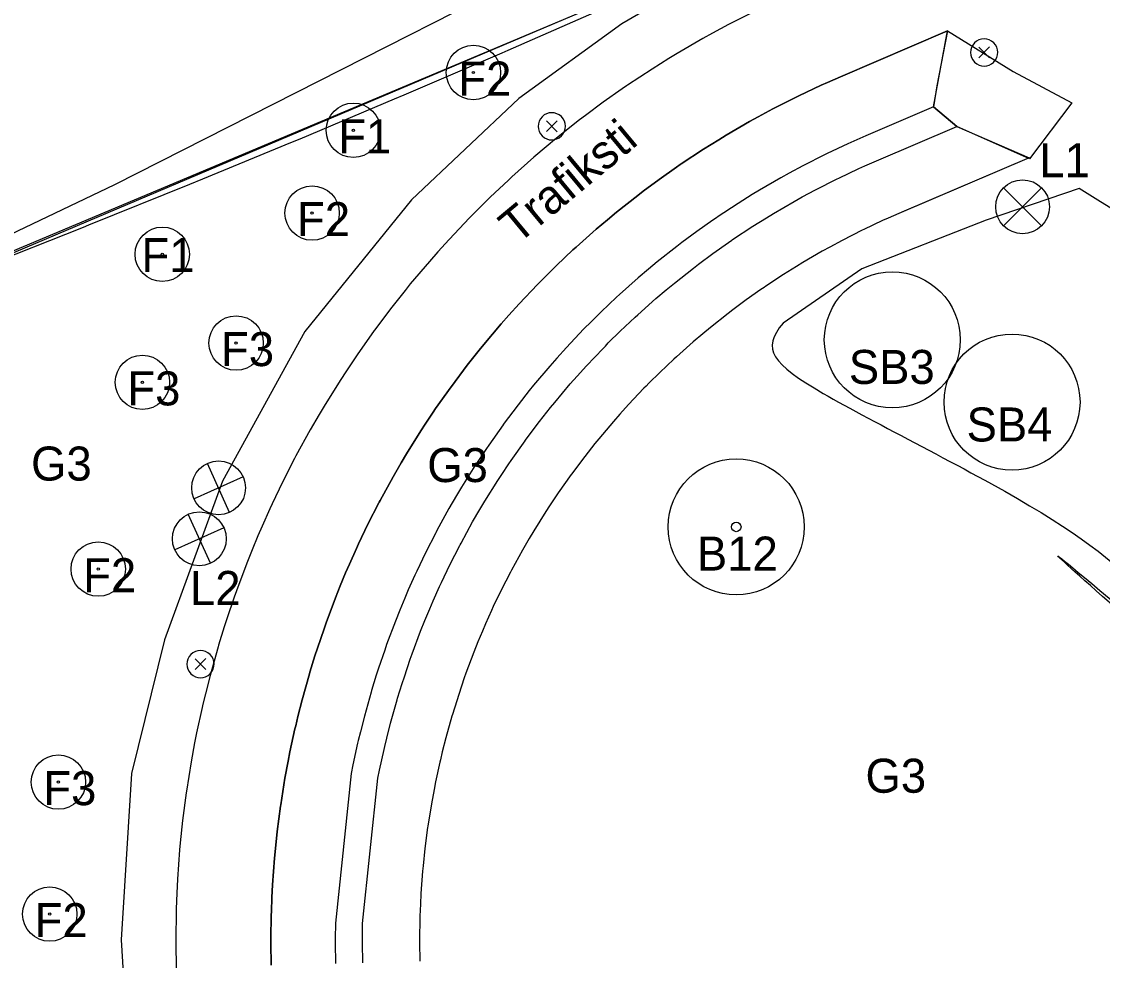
# Model space of a CAD drawing. Extents: x 0 to 512122, y 0 to 6212554.
# Drawn here: x 511727.9 to 511767.64, y 6211766.14 to 6211800.64 of the extents above; entities that cross this region are included whole.
import ezdxf

# ---------------------------------------------------------------- set-up
doc = ezdxf.new("R2010")
doc.units = 0
for name, color, linetype in [('_lights', 7, 'Continuous'), ('_Låge L1', 7, 'Continuous'), ('_Låge L2', 7, 'Continuous'), ('_ny fruit trees', 7, 'Continuous'), ('L40 jord udlagt muld og grøft', 7, 'Continuous'), ('MatrikelnummerMaster', 7, 'Continuous'), ('Skel', 7, 'Continuous'), ('TV_U_AFM_Symbl_Gul', 7, 'Continuous'), ('TV_U_LYS_Mastenummer', 7, 'Continuous')]:
    doc.layers.add(name, color=color, linetype=linetype)

# ---------------------------------------------------------------- blocks, each defined once
blk = doc.blocks.new('SOLITAIRE TREES')
at = {"layer": 'Skel'}
for radius in [2, 0.141]:
    blk.add_circle((0, 0), radius, dxfattribs=at)

msp = doc.modelspace()

# ---------------------------------------------------------------- linework, layer by layer
at = {"layer": '_lights'}
for p, q in [((511763.098, 6211799.706), (511763.492, 6211799.311)), ((511763.496, 6211799.71), (511763.102, 6211799.315)), ((511747.198, 6211796.991), (511747.592, 6211796.597)), ((511747.596, 6211796.995), (511747.202, 6211796.6)), ((511734.281, 6211777.225), (511734.675, 6211776.831)), ((511734.679, 6211777.229), (511734.285, 6211776.835))]:
    msp.add_line(p, q, dxfattribs=at)
for centre, start, end in [((511763.295, 6211799.509), 315.5636, 315), ((511763.295, 6211799.509), 315, 315.5636), ((511747.395, 6211796.794), 315.5636, 315), ((511747.395, 6211796.794), 315, 315.5636), ((511734.478, 6211777.028), 315.5636, 315), ((511734.478, 6211777.028), 315, 315.5636)]:
    msp.add_arc(centre, 0.5, start, end, dxfattribs=at)
at = {"layer": '_Låge L1'}
for p, q in [((511765.406, 6211794.536), (511764.008, 6211793.138)), ((511764.008, 6211794.536), (511765.406, 6211793.138))]:
    msp.add_line(p, q, dxfattribs=at)
msp.add_circle((511764.707, 6211793.837), 0.989, dxfattribs=at)
at = {"layer": '_Låge L2'}
for p, q in [((511735.549, 6211782.603), (511734.735, 6211784.406)), ((511736.043, 6211783.911), (511734.241, 6211783.098)), ((511734.841, 6211780.733), (511734.027, 6211782.535)), ((511735.335, 6211782.041), (511733.533, 6211781.227))]:
    msp.add_line(p, q, dxfattribs=at)
for centre in [(511735.142, 6211783.505), (511734.434, 6211781.634)]:
    msp.add_circle(centre, 0.989, dxfattribs=at)
at = {"layer": '_ny fruit trees'}
for centre, radius in [((511744.513, 6211798.772), 1), ((511744.513, 6211798.772), 0.0426), ((511740.097, 6211796.648), 1), ((511740.097, 6211796.648), 0.0426), ((511738.582, 6211793.605), 1), ((511738.582, 6211793.605), 0.0426), ((511733.071, 6211792.09), 1), ((511733.071, 6211792.09), 0.0426), ((511735.787, 6211788.829), 1), ((511735.787, 6211788.829), 0.0426), ((511732.34, 6211787.384), 1), ((511732.34, 6211787.384), 0.0426), ((511730.715, 6211780.52), 1), ((511730.715, 6211780.52), 0.0426), ((511729.251, 6211772.691), 1), ((511729.251, 6211772.691), 0.0426), ((511728.933, 6211767.84), 1), ((511728.933, 6211767.84), 0.0426)]:
    msp.add_circle(centre, radius, dxfattribs=at)
at = {"layer": 'L40 jord udlagt muld og grøft'}
for points in [[(511716.684, 6211807.008), (511745.321, 6211818.788), (511750.168, 6211811.842), (511756.678, 6211804.446), (511723.011, 6211790.293), (511716.684, 6211807.008)], [(511726.45, 6211791.621), (511730.172, 6211793.09), (511730.368, 6211793.168), (511734.084, 6211794.667), (511734.557, 6211794.861), (511737.801, 6211796.198), (511738.137, 6211796.337), (511741.615, 6211797.801), (511741.965, 6211797.948), (511745.576, 6211799.5), (511745.795, 6211799.594), (511749.456, 6211801.199), (511757.004, 6211804.634), (511758.258, 6211803.606), (511758.576, 6211803.35), (511758.674, 6211803.272), (511759.018, 6211803.002), (511759.055, 6211802.974), (511759.094, 6211802.943), (511759.162, 6211802.894)], [(511754.868, 6211801.026), (511753.899, 6211800.535), (511753.304, 6211800.216), (511752.945, 6211800.017), (511752.007, 6211799.471), (511751.701, 6211799.286), (511751.084, 6211798.899), (511750.178, 6211798.301), (511750.145, 6211798.279), (511749.987, 6211798.17), (511749.289, 6211797.677), (511748.64, 6211797.197), (511748.419, 6211797.028), (511747.567, 6211796.355), (511747.19, 6211796.043), (511746.736, 6211795.657), (511745.924, 6211794.936), (511745.798, 6211794.82), (511745.133, 6211794.192), (511744.601, 6211793.666), (511744.467, 6211793.531), (511744.364, 6211793.426), (511743.617, 6211792.638), (511743.2, 6211792.178), (511742.893, 6211791.829), (511742.192, 6211791), (511742.001, 6211790.765), (511741.516, 6211790.151), (511740.872, 6211789.296), (511740.863, 6211789.283), (511740.236, 6211788.397), (511740.135, 6211788.248), (511739.817, 6211787.773), (511739.635, 6211787.493), (511739.059, 6211786.573), (511738.836, 6211786.2), (511738.51, 6211785.636), (511737.988, 6211784.684), (511737.95, 6211784.613), (511737.934, 6211784.581), (511737.493, 6211783.718), (511737.111, 6211782.921), (511737.027, 6211782.737), (511736.742, 6211782.101), (511736.588, 6211781.744), (511736.371, 6211781.222), (511736.178, 6211780.739), (511735.797, 6211779.722), (511735.714, 6211779.489), (511735.445, 6211778.695), (511735.348, 6211778.394), (511735.142, 6211777.726), (511735.122, 6211777.659), (511734.83, 6211776.613), (511734.658, 6211775.938), (511734.567, 6211775.56), (511734.538, 6211775.435), (511734.334, 6211774.499), (511734.26, 6211774.128), (511734.132, 6211773.433), (511733.961, 6211772.361), (511733.952, 6211772.3), (511733.82, 6211771.284), (511733.733, 6211770.46), (511733.71, 6211770.204), (511733.63, 6211769.121), (511733.604, 6211768.612), (511733.582, 6211768.037), (511733.578, 6211767.89), (511733.565, 6211766.951), (511733.565, 6211766.759), (511733.579, 6211765.865)], [(511761.949, 6211800.299), (511758.014, 6211798.618), (511757.536, 6211798.41), (511757.3, 6211798.303), (511756.483, 6211797.92), (511756.408, 6211797.883), (511755.529, 6211797.437), (511754.988, 6211797.147), (511754.663, 6211796.967), (511753.811, 6211796.472), (511753.533, 6211796.303), (511752.973, 6211795.952), (511752.15, 6211795.409), (511752.121, 6211795.389), (511751.977, 6211795.29), (511751.344, 6211794.843), (511750.754, 6211794.407), (511750.554, 6211794.254), (511749.78, 6211793.642), (511749.438, 6211793.359), (511749.025, 6211793.009), (511748.288, 6211792.354), (511748.174, 6211792.249), (511747.57, 6211791.679), (511747.087, 6211791.201), (511746.965, 6211791.078), (511746.872, 6211790.983), (511746.194, 6211790.268), (511745.815, 6211789.85), (511745.536, 6211789.533), (511744.9, 6211788.78), (511744.727, 6211788.567), (511744.286, 6211788.01), (511743.702, 6211787.233), (511743.694, 6211787.222), (511743.124, 6211786.417), (511743.032, 6211786.282), (511742.743, 6211785.85), (511742.578, 6211785.597), (511742.056, 6211784.761), (511741.853, 6211784.423), (511741.557, 6211783.91), (511741.083, 6211783.046), (511741.049, 6211782.982), (511741.034, 6211782.953), (511740.634, 6211782.169), (511740.287, 6211781.445), (511740.21, 6211781.279), (511739.952, 6211780.701), (511739.812, 6211780.377), (511739.615, 6211779.903), (511739.44, 6211779.464), (511739.094, 6211778.542), (511739.019, 6211778.33), (511738.774, 6211777.609), (511738.686, 6211777.335), (511738.5, 6211776.729), (511738.482, 6211776.668), (511738.216, 6211775.719), (511738.06, 6211775.106), (511737.977, 6211774.762), (511737.951, 6211774.649), (511737.766, 6211773.8), (511737.699, 6211773.462), (511737.583, 6211772.831), (511737.427, 6211771.858), (511737.419, 6211771.803), (511737.299, 6211770.88), (511737.22, 6211770.132), (511737.199, 6211769.9), (511737.127, 6211768.917), (511737.103, 6211768.454), (511737.083, 6211767.932), (511737.08, 6211767.799), (511737.068, 6211766.947), (511737.068, 6211766.772), (511737.08, 6211765.961)], [(511737.08, 6211765.961), (511737.068, 6211766.772), (511737.068, 6211766.947), (511737.08, 6211767.799), (511737.083, 6211767.932), (511737.103, 6211768.454), (511737.127, 6211768.917), (511737.199, 6211769.9), (511737.22, 6211770.132), (511737.299, 6211770.88), (511737.419, 6211771.803), (511737.427, 6211771.858), (511737.583, 6211772.831), (511737.699, 6211773.462), (511737.766, 6211773.8), (511737.951, 6211774.649), (511737.977, 6211774.762), (511738.06, 6211775.106), (511738.216, 6211775.719), (511738.482, 6211776.668), (511738.5, 6211776.729), (511738.686, 6211777.335), (511738.774, 6211777.609), (511739.019, 6211778.33), (511739.094, 6211778.542), (511739.44, 6211779.464), (511739.615, 6211779.903), (511739.812, 6211780.377), (511739.952, 6211780.701), (511740.21, 6211781.279), (511740.287, 6211781.445), (511740.634, 6211782.169), (511741.034, 6211782.953), (511741.049, 6211782.982), (511741.083, 6211783.046), (511741.557, 6211783.91), (511741.853, 6211784.423), (511742.056, 6211784.761), (511742.578, 6211785.597), (511742.743, 6211785.85), (511743.032, 6211786.282), (511743.124, 6211786.417), (511743.694, 6211787.222), (511743.702, 6211787.233), (511744.286, 6211788.01), (511744.727, 6211788.567), (511744.9, 6211788.78), (511745.536, 6211789.533), (511745.815, 6211789.85), (511746.194, 6211790.268), (511746.872, 6211790.983), (511746.965, 6211791.078), (511747.087, 6211791.201), (511747.57, 6211791.679), (511748.174, 6211792.249), (511748.288, 6211792.354), (511749.025, 6211793.009), (511749.438, 6211793.359), (511749.78, 6211793.642), (511750.554, 6211794.254), (511750.754, 6211794.407), (511751.344, 6211794.843), (511751.977, 6211795.29), (511752.121, 6211795.389), (511752.15, 6211795.409), (511752.973, 6211795.952), (511753.533, 6211796.303), (511753.811, 6211796.472), (511754.663, 6211796.967), (511754.988, 6211797.147), (511755.529, 6211797.437), (511756.408, 6211797.883), (511756.483, 6211797.92), (511757.3, 6211798.303), (511757.536, 6211798.41), (511758.014, 6211798.618), (511761.949, 6211800.299), (511761.553, 6211798.279), (511761.434, 6211797.507), (511758.943, 6211796.443), (511758.498, 6211796.249), (511758.278, 6211796.15), (511757.517, 6211795.793), (511757.447, 6211795.759), (511756.629, 6211795.344), (511756.125, 6211795.073), (511755.822, 6211794.905), (511755.028, 6211794.444), (511754.769, 6211794.287), (511754.248, 6211793.96), (511753.481, 6211793.454), (511753.454, 6211793.435), (511753.32, 6211793.344), (511752.73, 6211792.927), (511752.181, 6211792.521), (511751.994, 6211792.378), (511751.274, 6211791.808), (511750.955, 6211791.545), (511750.57, 6211791.219), (511749.884, 6211790.609), (511749.777, 6211790.511), (511749.215, 6211789.98), (511748.765, 6211789.535), (511748.652, 6211789.42), (511748.565, 6211789.332), (511747.933, 6211788.665), (511747.581, 6211788.276), (511747.321, 6211787.981), (511746.728, 6211787.28), (511746.567, 6211787.082), (511746.156, 6211786.562), (511745.612, 6211785.839), (511745.604, 6211785.828), (511745.074, 6211785.079), (511744.988, 6211784.953), (511744.719, 6211784.551), (511744.565, 6211784.314), (511744.079, 6211783.536), (511743.89, 6211783.221), (511743.614, 6211782.744), (511743.173, 6211781.939), (511743.141, 6211781.879), (511743.127, 6211781.852), (511742.755, 6211781.122), (511742.432, 6211780.448), (511742.36, 6211780.293), (511742.119, 6211779.755), (511741.989, 6211779.453), (511741.805, 6211779.011), (511741.642, 6211778.603), (511741.32, 6211777.743), (511741.25, 6211777.546), (511741.022, 6211776.874), (511740.94, 6211776.62), (511740.767, 6211776.055), (511740.75, 6211775.998), (511740.502, 6211775.114), (511740.356, 6211774.543), (511740.28, 6211774.223), (511740.255, 6211774.117), (511740.083, 6211773.326), (511740.021, 6211773.012), (511739.44, 6211767.503), (511739.433, 6211766.943), (511739.433, 6211766.78), (511739.444, 6211766.025)], [(511761.949, 6211800.299), (511761.553, 6211798.279), (511761.434, 6211797.507), (511762.286, 6211796.784), (511764.951, 6211795.637)], [(511740.444, 6211766.052), (511740.433, 6211766.784), (511740.433, 6211766.941), (511740.44, 6211767.49), (511741.004, 6211772.83), (511741.063, 6211773.126), (511741.23, 6211773.892), (511741.253, 6211773.995), (511741.328, 6211774.304), (511741.469, 6211774.858), (511741.709, 6211775.714), (511741.725, 6211775.77), (511741.893, 6211776.317), (511741.973, 6211776.564), (511742.193, 6211777.214), (511742.261, 6211777.405), (511742.573, 6211778.238), (511742.732, 6211778.634), (511742.909, 6211779.062), (511743.035, 6211779.354), (511743.269, 6211779.876), (511743.338, 6211780.026), (511743.651, 6211780.679), (511744.012, 6211781.387), (511744.026, 6211781.412), (511744.057, 6211781.471), (511744.484, 6211782.251), (511744.752, 6211782.713), (511744.934, 6211783.018), (511745.406, 6211783.772), (511745.555, 6211784.001), (511745.815, 6211784.391), (511745.898, 6211784.513), (511746.412, 6211785.239), (511746.42, 6211785.249), (511746.947, 6211785.95), (511747.345, 6211786.453), (511747.501, 6211786.646), (511748.075, 6211787.325), (511748.327, 6211787.611), (511748.669, 6211787.988), (511749.281, 6211788.633), (511749.365, 6211788.719), (511749.474, 6211788.83), (511749.911, 6211789.261), (511750.455, 6211789.776), (511750.559, 6211789.871), (511751.224, 6211790.462), (511751.596, 6211790.778), (511751.905, 6211791.033), (511752.603, 6211791.585), (511752.784, 6211791.723), (511753.316, 6211792.117), (511753.888, 6211792.521), (511754.017, 6211792.609), (511754.044, 6211792.628), (511754.787, 6211793.118), (511755.292, 6211793.434), (511755.543, 6211793.587), (511756.312, 6211794.033), (511756.605, 6211794.196), (511757.093, 6211794.458), (511757.887, 6211794.86), (511757.954, 6211794.893), (511758.691, 6211795.24), (511758.905, 6211795.336), (511759.336, 6211795.524), (511762.286, 6211796.784), (511761.434, 6211797.507), (511758.943, 6211796.443), (511758.498, 6211796.249), (511758.278, 6211796.15), (511757.517, 6211795.793), (511757.447, 6211795.759), (511756.629, 6211795.344), (511756.125, 6211795.073), (511755.822, 6211794.905), (511755.028, 6211794.444), (511754.769, 6211794.287), (511754.248, 6211793.96), (511753.481, 6211793.454), (511753.454, 6211793.435), (511753.32, 6211793.344), (511752.73, 6211792.927), (511752.181, 6211792.521), (511751.994, 6211792.378), (511751.274, 6211791.808), (511750.955, 6211791.545), (511750.57, 6211791.219), (511749.884, 6211790.609), (511749.777, 6211790.511), (511749.215, 6211789.98), (511748.765, 6211789.535), (511748.652, 6211789.42), (511748.565, 6211789.332), (511747.933, 6211788.665), (511747.581, 6211788.276), (511747.321, 6211787.981), (511746.728, 6211787.28), (511746.567, 6211787.082), (511746.156, 6211786.562), (511745.612, 6211785.839), (511745.604, 6211785.828), (511745.074, 6211785.079), (511744.988, 6211784.953), (511744.719, 6211784.551), (511744.565, 6211784.314), (511744.079, 6211783.536), (511743.89, 6211783.221), (511743.614, 6211782.744), (511743.173, 6211781.939), (511743.141, 6211781.879), (511743.127, 6211781.852), (511742.755, 6211781.122), (511742.432, 6211780.448), (511742.36, 6211780.293), (511742.119, 6211779.755), (511741.989, 6211779.453), (511741.805, 6211779.011), (511741.642, 6211778.603), (511741.32, 6211777.743), (511741.25, 6211777.546), (511741.022, 6211776.874), (511740.94, 6211776.62), (511740.767, 6211776.055), (511740.75, 6211775.998), (511740.502, 6211775.114), (511740.356, 6211774.543), (511740.28, 6211774.223), (511740.255, 6211774.117), (511740.083, 6211773.326), (511740.021, 6211773.012), (511739.44, 6211767.503), (511739.433, 6211766.943), (511739.433, 6211766.78), (511739.444, 6211766.025)], [(511740.444, 6211766.052), (511740.433, 6211766.784), (511740.433, 6211766.941), (511740.44, 6211767.49), (511741.004, 6211772.83), (511741.063, 6211773.126), (511741.23, 6211773.892), (511741.253, 6211773.995), (511741.328, 6211774.304), (511741.469, 6211774.858), (511741.709, 6211775.714), (511741.725, 6211775.77), (511741.893, 6211776.317), (511741.973, 6211776.564), (511742.193, 6211777.214), (511742.261, 6211777.405), (511742.573, 6211778.238), (511742.732, 6211778.634), (511742.909, 6211779.062), (511743.035, 6211779.354), (511743.269, 6211779.876), (511743.338, 6211780.026), (511743.651, 6211780.679), (511744.012, 6211781.387), (511744.026, 6211781.412), (511744.057, 6211781.471), (511744.484, 6211782.251), (511744.752, 6211782.713), (511744.934, 6211783.018), (511745.406, 6211783.772), (511745.555, 6211784.001), (511745.815, 6211784.391), (511745.898, 6211784.513), (511746.412, 6211785.239), (511746.42, 6211785.249), (511746.947, 6211785.95), (511747.345, 6211786.453), (511747.501, 6211786.646), (511748.075, 6211787.325), (511748.327, 6211787.611), (511748.669, 6211787.988), (511749.281, 6211788.633), (511749.365, 6211788.719), (511749.474, 6211788.83), (511749.911, 6211789.261), (511750.455, 6211789.776), (511750.559, 6211789.871), (511751.224, 6211790.462), (511751.596, 6211790.778), (511751.905, 6211791.033), (511752.603, 6211791.585), (511752.784, 6211791.723), (511753.316, 6211792.117), (511753.888, 6211792.521), (511754.017, 6211792.609), (511754.044, 6211792.628), (511754.787, 6211793.118), (511755.292, 6211793.434), (511755.543, 6211793.587), (511756.312, 6211794.033), (511756.605, 6211794.196), (511757.093, 6211794.458), (511757.887, 6211794.86), (511757.954, 6211794.893), (511758.691, 6211795.24), (511758.905, 6211795.336), (511759.336, 6211795.524), (511762.286, 6211796.784), (511764.951, 6211795.637), (511760.162, 6211793.591), (511759.76, 6211793.415), (511759.561, 6211793.326), (511758.873, 6211793.003), (511758.81, 6211792.972), (511758.071, 6211792.597), (511757.616, 6211792.353), (511757.342, 6211792.201), (511756.625, 6211791.784), (511756.391, 6211791.642), (511755.92, 6211791.347), (511755.227, 6211790.89), (511755.202, 6211790.873), (511755.082, 6211790.79), (511754.548, 6211790.414), (511754.053, 6211790.047), (511753.883, 6211789.918), (511753.233, 6211789.403), (511752.945, 6211789.165), (511752.597, 6211788.87), (511751.977, 6211788.319), (511751.881, 6211788.231), (511751.373, 6211787.751), (511750.966, 6211787.349), (511750.864, 6211787.246), (511750.785, 6211787.166), (511750.215, 6211786.564), (511749.896, 6211786.212), (511749.661, 6211785.946), (511749.126, 6211785.312), (511748.98, 6211785.133), (511748.609, 6211784.663), (511748.118, 6211784.01), (511748.111, 6211784), (511747.632, 6211783.323), (511747.554, 6211783.21), (511747.311, 6211782.846), (511747.172, 6211782.633), (511746.732, 6211781.929), (511746.562, 6211781.645), (511746.313, 6211781.214), (511745.914, 6211780.486), (511745.885, 6211780.432), (511745.873, 6211780.408), (511745.536, 6211779.748), (511745.244, 6211779.139), (511745.179, 6211778.999), (511744.962, 6211778.513), (511744.844, 6211778.24), (511744.678, 6211777.841), (511744.531, 6211777.472), (511744.24, 6211776.696), (511744.177, 6211776.517), (511743.971, 6211775.911), (511743.897, 6211775.681), (511743.74, 6211775.171), (511743.725, 6211775.119), (511743.501, 6211774.32), (511743.369, 6211773.804), (511743.3, 6211773.515), (511743.278, 6211773.42), (511743.122, 6211772.705), (511743.066, 6211772.421), (511742.968, 6211771.89), (511742.837, 6211771.071), (511742.83, 6211771.025), (511742.729, 6211770.248), (511742.663, 6211769.619), (511742.645, 6211769.423), (511742.585, 6211768.596), (511742.564, 6211768.207), (511742.548, 6211767.767), (511742.545, 6211767.656), (511742.535, 6211766.938), (511742.535, 6211766.791), (511742.545, 6211766.108)], [(511764.951, 6211795.637), (511764.951, 6211795.637), (511764.032, 6211795.244), (511763.112, 6211794.851), (511762.192, 6211794.458), (511761.273, 6211794.065), (511760.353, 6211793.673), (511760.162, 6211793.591), (511759.76, 6211793.415), (511759.561, 6211793.326), (511758.873, 6211793.003), (511758.81, 6211792.972), (511758.071, 6211792.597), (511757.616, 6211792.353), (511757.342, 6211792.201), (511756.625, 6211791.784), (511756.391, 6211791.642), (511755.92, 6211791.347), (511755.227, 6211790.89), (511755.202, 6211790.873), (511755.082, 6211790.79), (511754.548, 6211790.414), (511754.053, 6211790.047), (511753.883, 6211789.918), (511753.233, 6211789.403), (511752.945, 6211789.165), (511752.597, 6211788.87), (511751.977, 6211788.319), (511751.881, 6211788.231), (511751.373, 6211787.751), (511750.966, 6211787.349), (511750.864, 6211787.246), (511750.785, 6211787.166), (511750.215, 6211786.564), (511749.896, 6211786.212), (511749.661, 6211785.946), (511749.126, 6211785.312), (511748.98, 6211785.133), (511748.609, 6211784.663), (511748.118, 6211784.01), (511748.111, 6211784), (511747.632, 6211783.323), (511747.554, 6211783.21), (511747.311, 6211782.846), (511747.172, 6211782.633), (511746.732, 6211781.929), (511746.562, 6211781.645), (511746.313, 6211781.214), (511745.914, 6211780.486), (511745.885, 6211780.432), (511745.873, 6211780.408), (511745.536, 6211779.748), (511745.244, 6211779.139), (511745.179, 6211778.999), (511744.962, 6211778.513), (511744.844, 6211778.24), (511744.678, 6211777.841), (511744.531, 6211777.472), (511744.24, 6211776.696), (511744.177, 6211776.517), (511743.971, 6211775.911), (511743.897, 6211775.681), (511743.74, 6211775.171), (511743.725, 6211775.119), (511743.501, 6211774.32), (511743.369, 6211773.804), (511743.3, 6211773.515), (511743.278, 6211773.42), (511743.122, 6211772.705), (511743.066, 6211772.421), (511742.968, 6211771.89), (511742.837, 6211771.071), (511742.83, 6211771.025), (511742.729, 6211770.248), (511742.663, 6211769.619), (511742.645, 6211769.423), (511742.585, 6211768.596), (511742.564, 6211768.207), (511742.548, 6211767.767), (511742.545, 6211767.656), (511742.535, 6211766.938), (511742.535, 6211766.791), (511742.545, 6211766.108)]]:
    msp.add_lwpolyline(points, dxfattribs=at)
for points in [[(511724.584, 6211790.9), (511722.995, 6211790.334), (511716.685, 6211807.008), (511745.435, 6211818.563), (511747.247, 6211815.371), (511749.591, 6211811.924), (511752.478, 6211808.405), (511754.722, 6211806.079), (511756.429, 6211804.372), (511725.419, 6211791.222)], [(511764.359, 6211798.812), (511766.518, 6211797.655), (511764.967, 6211795.6), (511762.286, 6211796.784), (511761.434, 6211797.507), (511761.949, 6211800.299)]]:
    msp.add_lwpolyline(points, close=True, dxfattribs=at)
at = {"layer": 'MatrikelnummerMaster'}
for points in [[(511709.039, 6211784.02), (511731.329, 6211794.65), (511753.839, 6211806.083), (511755.583, 6211803.583), (511754.025, 6211802.931), (511749.976, 6211800.563), (511746.182, 6211797.81), (511742.241, 6211794.091), (511738.319, 6211789.251), (511735.288, 6211783.752), (511733.159, 6211777.92), (511731.942, 6211773.006), (511731.564, 6211766.894), (511731.842, 6211762.252), (511732.411, 6211756.897), (511733.074, 6211752.945), (511728.666, 6211752.117)], [(511766.791, 6211794.513), (511763.364, 6211793.343), (511758.801, 6211791.557), (511755.899, 6211789.559)]]:
    msp.add_lwpolyline(points, dxfattribs=at)
for points in [[(511783.969, 6211783.784), (511774.35, 6211792.434), (511766.791, 6211794.513), (511783.969, 6211783.784), (511766.791, 6211794.513)], [(511755.899, 6211789.559), (511755.09, 6211788.598), (511755.885, 6211787.544), (511766.013, 6211782.577), (511769.863, 6211779.247), (511771.577, 6211776.373), (511774.889, 6211770.251), (511781.282, 6211768.198), (511755.899, 6211789.559), (511781.282, 6211768.198)], [(511728.666, 6211752.117), (511726.887, 6211763.158), (511723.863, 6211773.002), (511719.725, 6211779.29), (511709.29, 6211782.06), (511728.666, 6211752.117), (511709.29, 6211782.06)]]:
    msp.add_open_spline(points, degree=3, dxfattribs=at)
at = {"layer": 'TV_U_LYS_Mastenummer'}
for centre in [(511759.917, 6211788.946), (511764.319, 6211786.659)]:
    msp.add_circle(centre, 2.5, dxfattribs=at)

# ---------------------------------------------------------------- block references
at = {"layer": 'Skel', "xscale": 1.25, "yscale": 1.25}
msp.add_blockref('SOLITAIRE TREES', (511754.177, 6211782.07), dxfattribs=at)

# ---------------------------------------------------------------- texts
at = {"layer": 'TV_U_AFM_Symbl_Gul'}
for s, p in [('F2', (511743.959, 6211797.924)), ('F1', (511739.543, 6211795.799)), ('L1', (511765.324, 6211794.924)), ('F2', (511738.027, 6211792.757)), ('F1', (511732.308, 6211791.434)), ('F3', (511735.232, 6211787.98)), ('SB3', (511758.318, 6211787.325)), ('F3', (511731.786, 6211786.536)), ('SB4', (511762.648, 6211785.21)), ('G3', (511728.247, 6211783.773)), ('G3', (511742.815, 6211783.718)), ('B12', (511752.732, 6211780.464)), ('F2', (511730.161, 6211779.671)), ('L2', (511734.089, 6211779.201)), ('G3', (511758.931, 6211772.3)), ('F3', (511728.696, 6211771.843)), ('F2', (511728.379, 6211766.992))]:
    msp.add_text(s, height=1.25, dxfattribs=at).set_placement(p)
msp.add_text('Trafiksti', height=1.25, rotation=39.7394, dxfattribs=at).set_placement((511746.128, 6211792.427))

doc.saveas('drawing.dxf')
